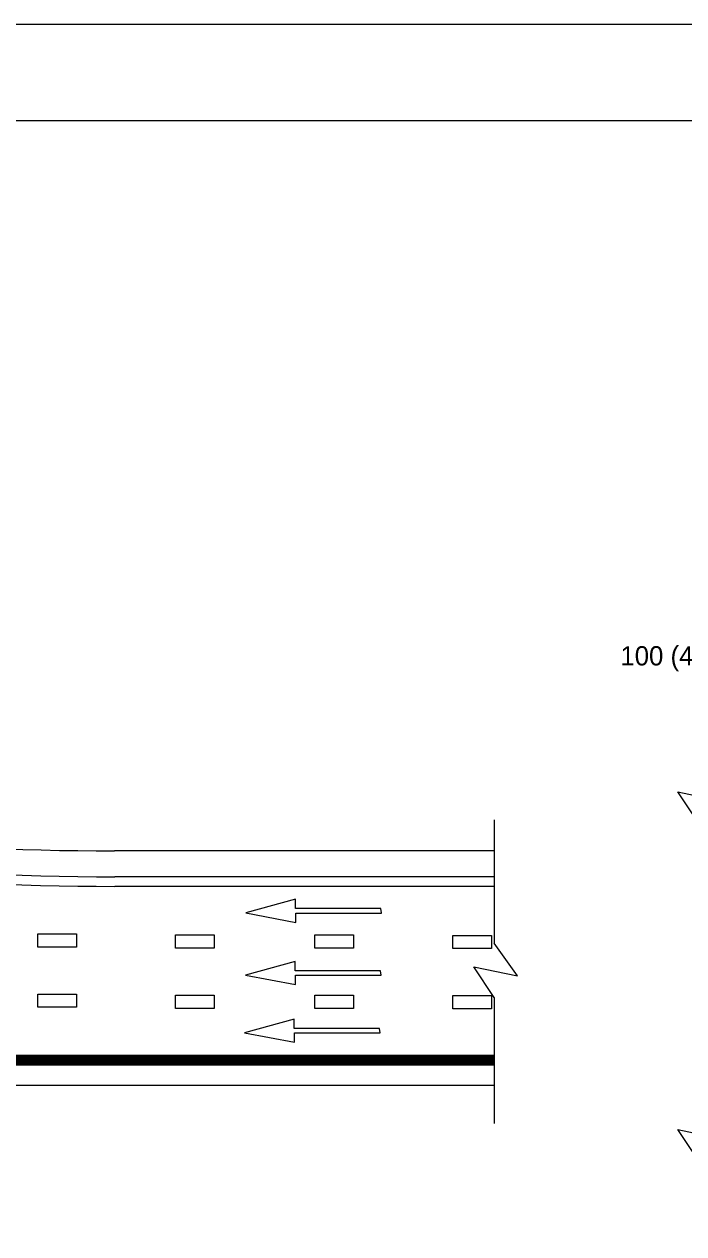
# Model space of a CAD drawing. Extents: x 639362 to 641108, y 298458 to 299646.
# Drawn here: x 639739 to 639841.8, y 299457.2 to 299645.6 of the extents above; entities that cross this region are included whole.
import ezdxf

# ---------------------------------------------------------------- set-up
doc = ezdxf.new("R2010")
doc.units = 0
for name, color, linetype in [('1', 7, 'Continuous'), ('2', 7, 'Continuous'), ('PLT-BNDY', 7, 'Continuous')]:
    doc.layers.add(name, color=color, linetype=linetype)

msp = doc.modelspace()

# ---------------------------------------------------------------- linework, layer by layer
at = {"layer": '1'}
msp.add_line((639402.31, 299630.63), (640188.31, 299630.63), dxfattribs=at)
at = {"layer": '2'}
for p, q in [((639843.44, 299522.15), (639840.87, 299526.02)), ((639840.87, 299526.02), (639846.39, 299524.88)), ((639812.25, 299521.68), (639812.25, 299502.46)), ((639812.25, 299516.84), (639753.05, 299516.84)), ((639812.25, 299512.81), (639753.12, 299512.81)), ((639812.25, 299511.31), (639753.12, 299511.31)), ((639781.25, 299509.3), (639773.52, 299507.18)), ((639781.25, 299507.85), (639781.25, 299509.3)), ((639794.57, 299507.85), (639781.25, 299507.85)), ((639794.65, 299507.18), (639794.57, 299507.85)), ((639773.52, 299507.18), (639781.33, 299505.7)), ((639781.33, 299505.7), (639781.33, 299507.15)), ((639781.33, 299507.15), (639794.65, 299507.15)), ((639794.65, 299507.15), (639794.65, 299507.18)), ((639741.13, 299501.86), (639741.13, 299503.93)), ((639741.13, 299503.93), (639747.14, 299503.93)), ((639747.14, 299503.93), (639747.14, 299501.86)), ((639762.58, 299501.67), (639762.58, 299503.74)), ((639762.58, 299503.74), (639768.59, 299503.74)), ((639768.59, 299503.74), (639768.59, 299501.67)), ((639784.28, 299501.67), (639784.28, 299503.74)), ((639784.28, 299503.74), (639790.29, 299503.74)), ((639790.29, 299503.74), (639790.29, 299501.67)), ((639805.8, 299501.61), (639805.8, 299503.68)), ((639805.8, 299503.68), (639811.81, 299503.68)), ((639811.81, 299503.68), (639811.81, 299501.61)), ((639815.89, 299497.36), (639812.25, 299502.46)), ((639747.14, 299501.86), (639741.13, 299501.86)), ((639768.59, 299501.67), (639762.58, 299501.67)), ((639790.29, 299501.67), (639784.28, 299501.67)), ((639811.81, 299501.61), (639805.8, 299501.61)), ((639781.21, 299499.61), (639773.49, 299497.5)), ((639781.21, 299498.17), (639781.21, 299499.61)), ((639812.25, 299493.99), (639809.07, 299498.76)), ((639809.07, 299498.76), (639815.89, 299497.36)), ((639773.49, 299497.5), (639781.29, 299496.02)), ((639794.54, 299498.17), (639781.21, 299498.17)), ((639781.29, 299496.02), (639781.29, 299497.46)), ((639781.29, 299497.46), (639794.62, 299497.46)), ((639794.62, 299497.5), (639794.54, 299498.17)), ((639794.62, 299497.46), (639794.62, 299497.5)), ((639741.13, 299492.47), (639741.13, 299494.53)), ((639741.13, 299494.53), (639747.14, 299494.53)), ((639747.14, 299494.53), (639747.14, 299492.47)), ((639762.58, 299492.28), (639762.58, 299494.35)), ((639762.58, 299494.35), (639768.59, 299494.35)), ((639768.59, 299494.35), (639768.59, 299492.28)), ((639784.28, 299492.28), (639784.28, 299494.35)), ((639784.28, 299494.35), (639790.29, 299494.35)), ((639790.29, 299494.35), (639790.29, 299492.28)), ((639805.8, 299492.22), (639805.8, 299494.29)), ((639805.8, 299494.29), (639811.81, 299494.29)), ((639811.81, 299494.29), (639811.81, 299492.22)), ((639812.25, 299493.99), (639812.25, 299474.38)), ((639747.14, 299492.47), (639741.13, 299492.47)), ((639768.59, 299492.28), (639762.58, 299492.28)), ((639790.29, 299492.28), (639784.28, 299492.28)), ((639811.81, 299492.22), (639805.8, 299492.22)), ((639781.05, 299490.63), (639773.32, 299488.51)), ((639781.05, 299489.18), (639781.05, 299490.63)), ((639794.37, 299489.18), (639781.05, 299489.18)), ((639794.45, 299488.51), (639794.37, 299489.18)), ((639773.32, 299488.51), (639781.13, 299487.03)), ((639781.13, 299487.03), (639781.13, 299488.48)), ((639781.13, 299488.48), (639794.45, 299488.48)), ((639794.45, 299488.48), (639794.45, 299488.51)), ((639511.24, 299484.99), (639812.25, 299484.99)), ((639511.24, 299484.84), (639812.25, 299484.84)), ((639511.24, 299484.69), (639812.25, 299484.69)), ((639511.24, 299484.54), (639812.25, 299484.54)), ((639511.24, 299484.39), (639812.25, 299484.39)), ((639511.24, 299484.24), (639812.25, 299484.24)), ((639511.24, 299484.09), (639812.25, 299484.09)), ((639511.24, 299483.94), (639812.25, 299483.94)), ((639511.24, 299483.79), (639812.25, 299483.79)), ((639511.24, 299483.64), (639812.25, 299483.64)), ((639511.24, 299483.49), (639812.25, 299483.49)), ((639511.24, 299480.35), (639812.25, 299480.35)), ((639843.44, 299469.54), (639840.87, 299473.41)), ((639840.87, 299473.41), (639846.39, 299472.28))]:
    msp.add_line(p, q, dxfattribs=at)
for centre, radius, start in [((639753.05, 299972.54), 455.7, 258.5199), ((639753.12, 299971.81), 459, 258.4765), ((639753.12, 299971.81), 460.5, 258.4765)]:
    msp.add_arc(centre, radius, start, 270, dxfattribs=at)
at = {"layer": 'PLT-BNDY'}
msp.add_lwpolyline([(639362.31, 299645.63), (640203.31, 299645.63), (640203.31, 299051.63), (639362.31, 299051.63)], close=True, dxfattribs=at)

# ---------------------------------------------------------------- texts
at = {"layer": '2'}
msp.add_text('100 (4")', height=3, dxfattribs=at).set_placement((639831.91, 299545.73))

doc.saveas('drawing.dxf')
